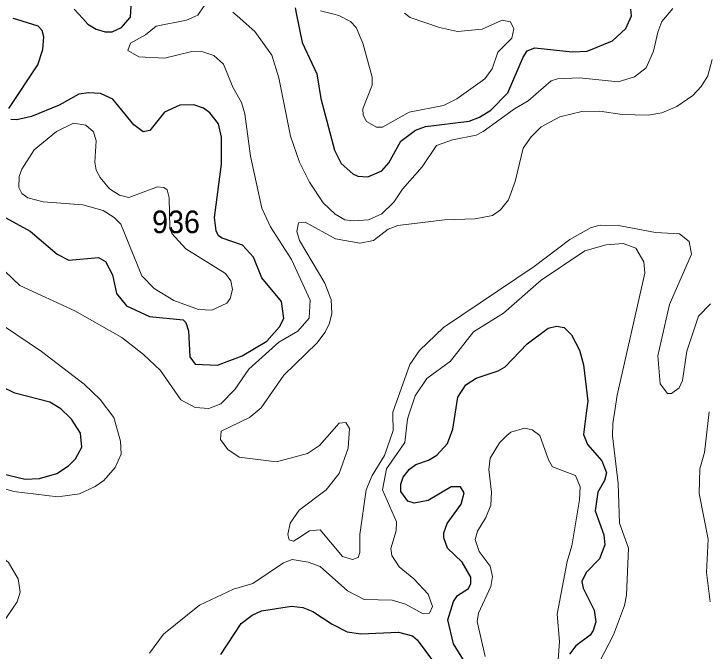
# Model space of a CAD drawing. Extents: x 473.9 to 500, y 7733.1 to 7760.8.
# Drawn here: x 476.736 to 479.198, y 7748.751 to 7751.009 of the extents above; entities that cross this region are included whole.
import ezdxf

# ---------------------------------------------------------------- set-up
doc = ezdxf.new("R2010")
doc.units = 0
doc.header["$LTSCALE"] = 0.032
doc.layers.add('1', color=7, linetype='Continuous', lineweight=25)
doc.layers.add('2', color=7, linetype='Continuous', lineweight=13)
doc.layers.add('21', color=7, linetype='Continuous')

msp = doc.modelspace()

# ---------------------------------------------------------------- linework, layer by layer
at = {"layer": '1'}
for points in [[(476.9506, 7751.0253), (476.9804, 7750.9926), (476.9983, 7750.9731), (477.028, 7750.9548), (477.0604, 7750.9459), (477.0852, 7750.9461), (477.1178, 7750.9614), (477.1477, 7750.9955), (477.1496, 7750.9976), (477.1535, 7751.0577)], [(477.7337, 7751.0307), (477.7388, 7751.0055), (477.7588, 7750.9076), (477.8111, 7750.797), (477.8242, 7750.7096), (477.8735, 7750.5265), (477.897, 7750.4792), (477.9387, 7750.4422), (477.9557, 7750.4344), (477.9915, 7750.4312), (478.0406, 7750.4534), (478.0662, 7750.4811), (478.1079, 7750.5582), (478.1602, 7750.5976), (478.1961, 7750.6104), (478.3503, 7750.6289), (478.3875, 7750.6433), (478.4279, 7750.6679), (478.4881, 7750.7296), (478.5418, 7750.8559), (478.5567, 7750.8785), (478.5836, 7750.8885), (478.7162, 7750.8749), (478.7688, 7750.8772), (478.8587, 7750.9142), (478.9062, 7750.9579), (478.9256, 7751.0025), (478.9236, 7751.0256)], [(476.8396, 7750.8827), (476.8422, 7750.928), (476.8368, 7750.9501), (476.8231, 7750.9653), (476.7469, 7750.9887), (476.7341, 7750.9926)], [(476.7189, 7750.6734), (476.8216, 7750.8291), (476.8396, 7750.8827)], [(476.6568, 7750.3141), (476.7941, 7750.2398), (476.8895, 7750.1577), (476.9312, 7750.1368), (477.0367, 7750.1463), (477.0615, 7750.132), (477.0863, 7750.0842), (477.1005, 7750.0188), (477.1363, 7749.9744), (477.2171, 7749.9369), (477.3369, 7749.9248), (477.3462, 7749.9154), (477.3551, 7749.8859), (477.3605, 7749.7941), (477.3791, 7749.7685), (477.4579, 7749.7641), (477.5456, 7749.7979), (477.633, 7749.8495), (477.6777, 7749.9002), (477.693, 7749.9298), (477.6849, 7749.9899), (477.6155, 7750.074), (477.5861, 7750.1469), (477.547, 7750.1901), (477.4749, 7750.2139), (477.4625, 7750.2228), (477.4532, 7750.2403), (477.4478, 7750.2873), (477.4727, 7750.477), (477.4727, 7750.5719), (477.4624, 7750.6195), (477.4315, 7750.6587), (477.4086, 7750.675), (477.3746, 7750.6868), (477.3244, 7750.6862), (477.2704, 7750.661), (477.2187, 7750.5954), (477.1954, 7750.5912), (477.1615, 7750.616), (477.087, 7750.7072), (477.0433, 7750.727), (477.0007, 7750.7295), (476.9666, 7750.7241), (476.897, 7750.6852), (476.7986, 7750.645), (476.7469, 7750.6339), (476.7251, 7750.6347)], [(478.3749, 7748.6481), (478.2948, 7748.7769), (478.2751, 7748.8616), (478.2954, 7748.9269), (478.3095, 7748.9481), (478.3481, 7748.9729), (478.3569, 7748.9905), (478.3568, 7749.0127), (478.3261, 7749.0668), (478.2736, 7749.1163), (478.2607, 7749.1527), (478.2609, 7749.1703), (478.2726, 7749.2029), (478.322, 7749.2716), (478.3326, 7749.3122), (478.3195, 7749.3332), (478.287, 7749.3338), (478.2053, 7749.2845), (478.1562, 7749.2752), (478.1334, 7749.2825), (478.1089, 7749.3163), (478.1087, 7749.3433), (478.1171, 7749.3673), (478.1393, 7749.3963), (478.1613, 7749.4128), (478.2069, 7749.4284), (478.236, 7749.4459), (478.2735, 7749.4866), (478.2923, 7749.5374), (478.3007, 7749.5905), (478.3103, 7749.6515), (478.3393, 7749.6951), (478.3757, 7749.7188), (478.4537, 7749.7444), (478.4777, 7749.7591), (478.5558, 7749.8404), (478.631, 7749.895), (478.6605, 7749.9029), (478.6876, 7749.8983), (478.7129, 7749.872), (478.7414, 7749.8177), (478.7558, 7749.7653), (478.7712, 7749.6366)], [(476.6865, 7749.3822), (476.7768, 7749.361), (476.8273, 7749.3631), (476.8885, 7749.3809), (476.9303, 7749.4073), (476.9553, 7749.432), (476.9775, 7749.4742), (476.9722, 7749.5232), (476.9408, 7749.5737), (476.9366, 7749.5778), (476.9029, 7749.6103), (476.864, 7749.6336), (476.7396, 7749.6647), (476.6913, 7749.6883)], [(478.7712, 7749.6366), (478.7659, 7749.5949), (478.7563, 7749.5189), (478.7706, 7749.4833), (478.821, 7749.4254), (478.8377, 7749.3829), (478.8305, 7749.3563), (478.8067, 7749.3148), (478.7969, 7749.2481), (478.828, 7749.1638), (478.8314, 7749.128), (478.8132, 7749.0787), (478.7649, 7749.0296), (478.7502, 7748.9979), (478.7543, 7748.9747), (478.7932, 7748.896), (478.7994, 7748.8545), (478.7903, 7748.824), (478.7792, 7748.808), (478.7282, 7748.7695), (478.7069, 7748.7402)], [(477.4697, 7748.7397), (477.5418, 7748.8495), (477.5817, 7748.8787), (477.6146, 7748.8942), (477.7213, 7748.9109), (477.7612, 7748.9062), (477.7969, 7748.8918), (477.8648, 7748.8462), (477.9181, 7748.82), (477.9667, 7748.812), (478.1001, 7748.8184), (478.1497, 7748.8053), (478.1666, 7748.7915), (478.3092, 7748.5985)]]:
    msp.add_lwpolyline(points, dxfattribs=at)
at = {"layer": '2'}
for points in [[(477.4116, 7751.0371), (477.3891, 7751.0044), (477.3778, 7750.9994), (477.3484, 7750.9863), (477.2409, 7750.966), (477.2036, 7750.935), (477.1501, 7750.9049), (477.1401, 7750.8789), (477.18, 7750.8566), (477.2707, 7750.8524), (477.3677, 7750.8757), (477.4062, 7750.8751), (477.4456, 7750.8616), (477.4795, 7750.8313), (477.5126, 7750.7494), (477.543, 7750.6951), (477.5554, 7750.6544), (477.5758, 7750.5054), (477.6151, 7750.321), (477.646, 7750.2546), (477.7206, 7750.1388), (477.787, 7749.9946), (477.7828, 7749.9309), (477.7428, 7749.8846), (477.676, 7749.8459), (477.5695, 7749.7507), (477.5198, 7749.6777), (477.4704, 7749.627), (477.4282, 7749.611), (477.3789, 7749.6141), (477.3283, 7749.6421), (477.256, 7749.7457), (477.1966, 7749.8028), (477.1194, 7749.8624), (476.9528, 7749.9571), (476.7581, 7750.0463), (476.7055, 7750.0959)], [(479.0721, 7751.0281), (479.0341, 7750.9817), (479.0189, 7750.9449), (479.0043, 7750.8775), (478.9783, 7750.8183), (478.9363, 7750.7858), (478.8783, 7750.7686), (478.7423, 7750.7826), (478.6642, 7750.7787), (478.6414, 7750.7715), (478.5602, 7750.7007), (478.5111, 7750.6724), (478.4005, 7750.5921), (478.3752, 7750.5797), (478.2917, 7750.5623), (478.2353, 7750.5424), (478.1836, 7750.467), (478.1148, 7750.3884), (478.0838, 7750.3417), (478.0404, 7750.3009), (477.9942, 7750.2791), (477.9396, 7750.2753), (477.9096, 7750.2798), (477.8761, 7750.2992), (477.8325, 7750.3399), (477.7847, 7750.4128), (477.7489, 7750.484), (477.717, 7750.5753), (477.6761, 7750.7825), (477.6514, 7750.8624), (477.5902, 7750.9471), (477.5277, 7751.0019)], [(478.1216, 7751.012), (478.1418, 7750.996), (478.2456, 7750.9608), (478.3089, 7750.9466), (478.3963, 7750.9552), (478.4681, 7750.9863), (478.4975, 7750.9815), (478.509, 7750.9562), (478.5015, 7750.9236), (478.4523, 7750.8738), (478.4317, 7750.8142), (478.4061, 7750.7794), (478.3074, 7750.7076), (478.2595, 7750.6848), (478.1379, 7750.6609), (478.043, 7750.6072), (478.0216, 7750.6072), (477.9868, 7750.6282), (477.9751, 7750.6497), (477.9737, 7750.6732), (478.0064, 7750.7568), (478.0073, 7750.7847), (477.9738, 7750.9048), (477.9496, 7750.9605), (477.9301, 7750.9827), (477.8885, 7751.0033), (477.8713, 7751.0077), (477.8233, 7751.0201)], [(477.5277, 7751.0019), (477.5125, 7751.0153)], [(479.2118, 7750.8475), (479.1962, 7750.7901), (479.1731, 7750.7514), (479.143, 7750.7195), (479.0874, 7750.6807), (479.0341, 7750.658), (478.9854, 7750.65), (478.8932, 7750.6532), (478.8144, 7750.6643), (478.7501, 7750.6628), (478.6723, 7750.6449), (478.6054, 7750.6091), (478.5702, 7750.5737), (478.5418, 7750.5332), (478.5142, 7750.4154), (478.4899, 7750.3506), (478.4612, 7750.315), (478.4332, 7750.2948), (478.3718, 7750.2829), (478.2633, 7750.2799), (478.0977, 7750.2597), (478.0633, 7750.2465), (478.0119, 7750.2063), (477.9632, 7750.1965), (477.8773, 7750.2117)], [(477.8773, 7750.2117), (477.7691, 7750.2717), (477.7461, 7750.2682), (477.7397, 7750.238), (477.7493, 7750.2057), (477.8388, 7750.0552), (477.8582, 7750.0056), (477.8616, 7749.9968), (477.8634, 7749.9475), (477.856, 7749.9137), (477.8406, 7749.8815), (477.8104, 7749.8425), (477.6938, 7749.7292), (477.613, 7749.6131), (477.5778, 7749.5838), (477.5718, 7749.5788), (477.471, 7749.5302), (477.4687, 7749.5007), (477.4948, 7749.4651), (477.5349, 7749.4386), (477.667, 7749.4225), (477.7779, 7749.451), (477.8204, 7749.4804), (477.8895, 7749.5593), (477.9134, 7749.5616), (477.9261, 7749.5406), (477.9221, 7749.4705), (477.8902, 7749.3808), (477.8431, 7749.3223), (477.7474, 7749.2505), (477.7161, 7749.2045), (477.7083, 7749.1649), (477.7121, 7749.1455), (477.7283, 7749.1409), (477.7436, 7749.1507), (477.7847, 7749.177), (477.8221, 7749.1813), (477.9011, 7749.0871), (477.9374, 7749.0756), (477.9569, 7749.0834), (477.963, 7749.1005), (477.9624, 7749.1643), (477.9858, 7749.323), (478.0063, 7749.3733), (478.0506, 7749.4441), (478.0813, 7749.5326), (478.08, 7749.5885), (478.0798, 7749.5975), (478.1404, 7749.7668), (478.175, 7749.8159), (478.2595, 7749.8974), (478.5811, 7750.114), (478.7074, 7750.2103), (478.7826, 7750.2522), (478.8154, 7750.2607), (478.8803, 7750.2598), (479.0112, 7750.2341), (479.0967, 7750.2293), (479.1305, 7750.2024), (479.1393, 7750.1581), (479.0611, 7749.9791), (479.0197, 7749.798), (479.0276, 7749.6978), (479.0535, 7749.6646), (479.0676, 7749.6635), (479.0949, 7749.6846), (479.1066, 7749.7105), (479.1224, 7749.814), (479.1641, 7749.9378), (479.2057, 7749.9821)], [(477.2168, 7748.7445), (477.2665, 7748.8115), (477.3944, 7748.9143), (477.5146, 7748.9703), (477.5831, 7748.9909), (477.6927, 7749.0646), (477.7235, 7749.0756), (477.7804, 7749.0666), (477.8224, 7749.0515), (477.919, 7748.9654), (477.9781, 7748.9336), (478.0773, 7748.9313), (478.1245, 7748.9178), (478.1871, 7748.8836), (478.2102, 7748.8857), (478.2212, 7748.9093), (478.2055, 7748.9529), (478.154, 7749.0076), (478.1026, 7749.0495), (478.076, 7749.0904), (478.0726, 7749.115), (478.0918, 7749.1777), (478.0926, 7749.2099), (478.0436, 7749.323), (478.0578, 7749.3974), (478.1229, 7749.4908), (478.1319, 7749.5728), (478.1372, 7749.589), (478.1592, 7749.6563), (478.2003, 7749.7172), (478.2839, 7749.7784), (478.3656, 7749.8823), (478.4725, 7749.9485), (478.6064, 7750.0654), (478.7608, 7750.1691), (478.8358, 7750.1906), (478.8969, 7750.1956), (478.9409, 7750.1785), (478.9701, 7750.1303), (478.9737, 7750.0906), (478.8748, 7749.658), (478.8653, 7749.5958), (478.8596, 7749.5583), (478.8589, 7749.5138), (478.8789, 7749.3455), (478.8831, 7749.2045), (478.9159, 7749.1161), (478.9084, 7748.9499), (478.9008, 7748.9129), (478.8627, 7748.8095), (478.8117, 7748.7109)], [(476.6994, 7749.904), (476.8348, 7749.8133), (476.9858, 7749.6975), (477.0425, 7749.6424), (477.0913, 7749.5793), (477.0913, 7749.5792), (477.1147, 7749.4951), (477.1173, 7749.4495), (477.0959, 7749.4017), (477.0554, 7749.3554), (477.0252, 7749.3344), (476.9689, 7749.3087), (476.8928, 7749.2976), (476.7368, 7749.3163), (476.6017, 7749.3561)], [(479.2046, 7748.9254), (479.1918, 7749.0303), (479.1979, 7749.1483), (479.166, 7749.3096), (479.1682, 7749.397), (479.1846, 7749.4554), (479.202, 7749.599)], [(478.6635, 7748.689), (478.6708, 7748.7855), (478.6627, 7748.8819), (478.6981, 7749.0685), (478.7142, 7749.1247), (478.7415, 7749.2872), (478.7439, 7749.3338), (478.7278, 7749.374), (478.6466, 7749.4045), (478.6314, 7749.4287), (478.6008, 7749.5147), (478.5735, 7749.5356), (478.5469, 7749.5412), (478.4987, 7749.5267), (478.4842, 7749.5155), (478.4585, 7749.4898), (478.4255, 7749.4351), (478.4207, 7749.3949), (478.4295, 7749.3145), (478.4271, 7749.2679), (478.4094, 7749.2244), (478.3797, 7749.1762), (478.3717, 7749.1473), (478.3861, 7749.1046), (478.4255, 7749.0524), (478.4328, 7749.0154), (478.4271, 7748.98), (478.3837, 7748.8852), (478.3789, 7748.8562), (478.407, 7748.7324)], [(476.1676, 7749.2042), (476.3787, 7749.1673), (476.4763, 7749.1583), (476.6156, 7749.1206), (476.6891, 7749.0888), (476.7173, 7749.0656), (476.7516, 7749.0074), (476.7588, 7748.9605), (476.7482, 7748.9262), (476.6585, 7748.7956), (476.6219, 7748.7077)]]:
    msp.add_lwpolyline(points, dxfattribs=at)
msp.add_lwpolyline([(477.2968, 7750.2307), (477.2893, 7750.2508), (477.2869, 7750.357), (477.2796, 7750.3861), (477.2677, 7750.3941), (477.2455, 7750.3966), (477.1436, 7750.3581), (477.1104, 7750.3671), (477.0758, 7750.3898), (477.042, 7750.429), (477.0277, 7750.4556), (477.0232, 7750.484), (477.0287, 7750.5592), (477.0191, 7750.5911), (476.9919, 7750.6153), (476.9482, 7750.6224), (476.887, 7750.5925), (476.8079, 7750.5276), (476.7641, 7750.4587), (476.7556, 7750.4326), (476.7545, 7750.3945), (476.7648, 7750.373), (476.7854, 7750.3575), (476.8402, 7750.3429), (476.9807, 7750.3329), (477.0531, 7750.3121), (477.0923, 7750.2881), (477.1153, 7750.2636), (477.19, 7750.081), (477.2341, 7750.0358), (477.3033, 7749.9934), (477.3908, 7749.9617), (477.4384, 7749.9589), (477.4912, 7749.9842), (477.5033, 7750.0002), (477.5113, 7750.0327), (477.5055, 7750.0638), (477.4871, 7750.0895), (477.3462, 7750.1768)], close=True, dxfattribs=at)

# ---------------------------------------------------------------- texts
at = {"layer": '21', "width": 0.95}
msp.add_text('936', height=0.08, dxfattribs=at).set_placement((477.2265, 7750.2322))

doc.saveas('drawing.dxf')
